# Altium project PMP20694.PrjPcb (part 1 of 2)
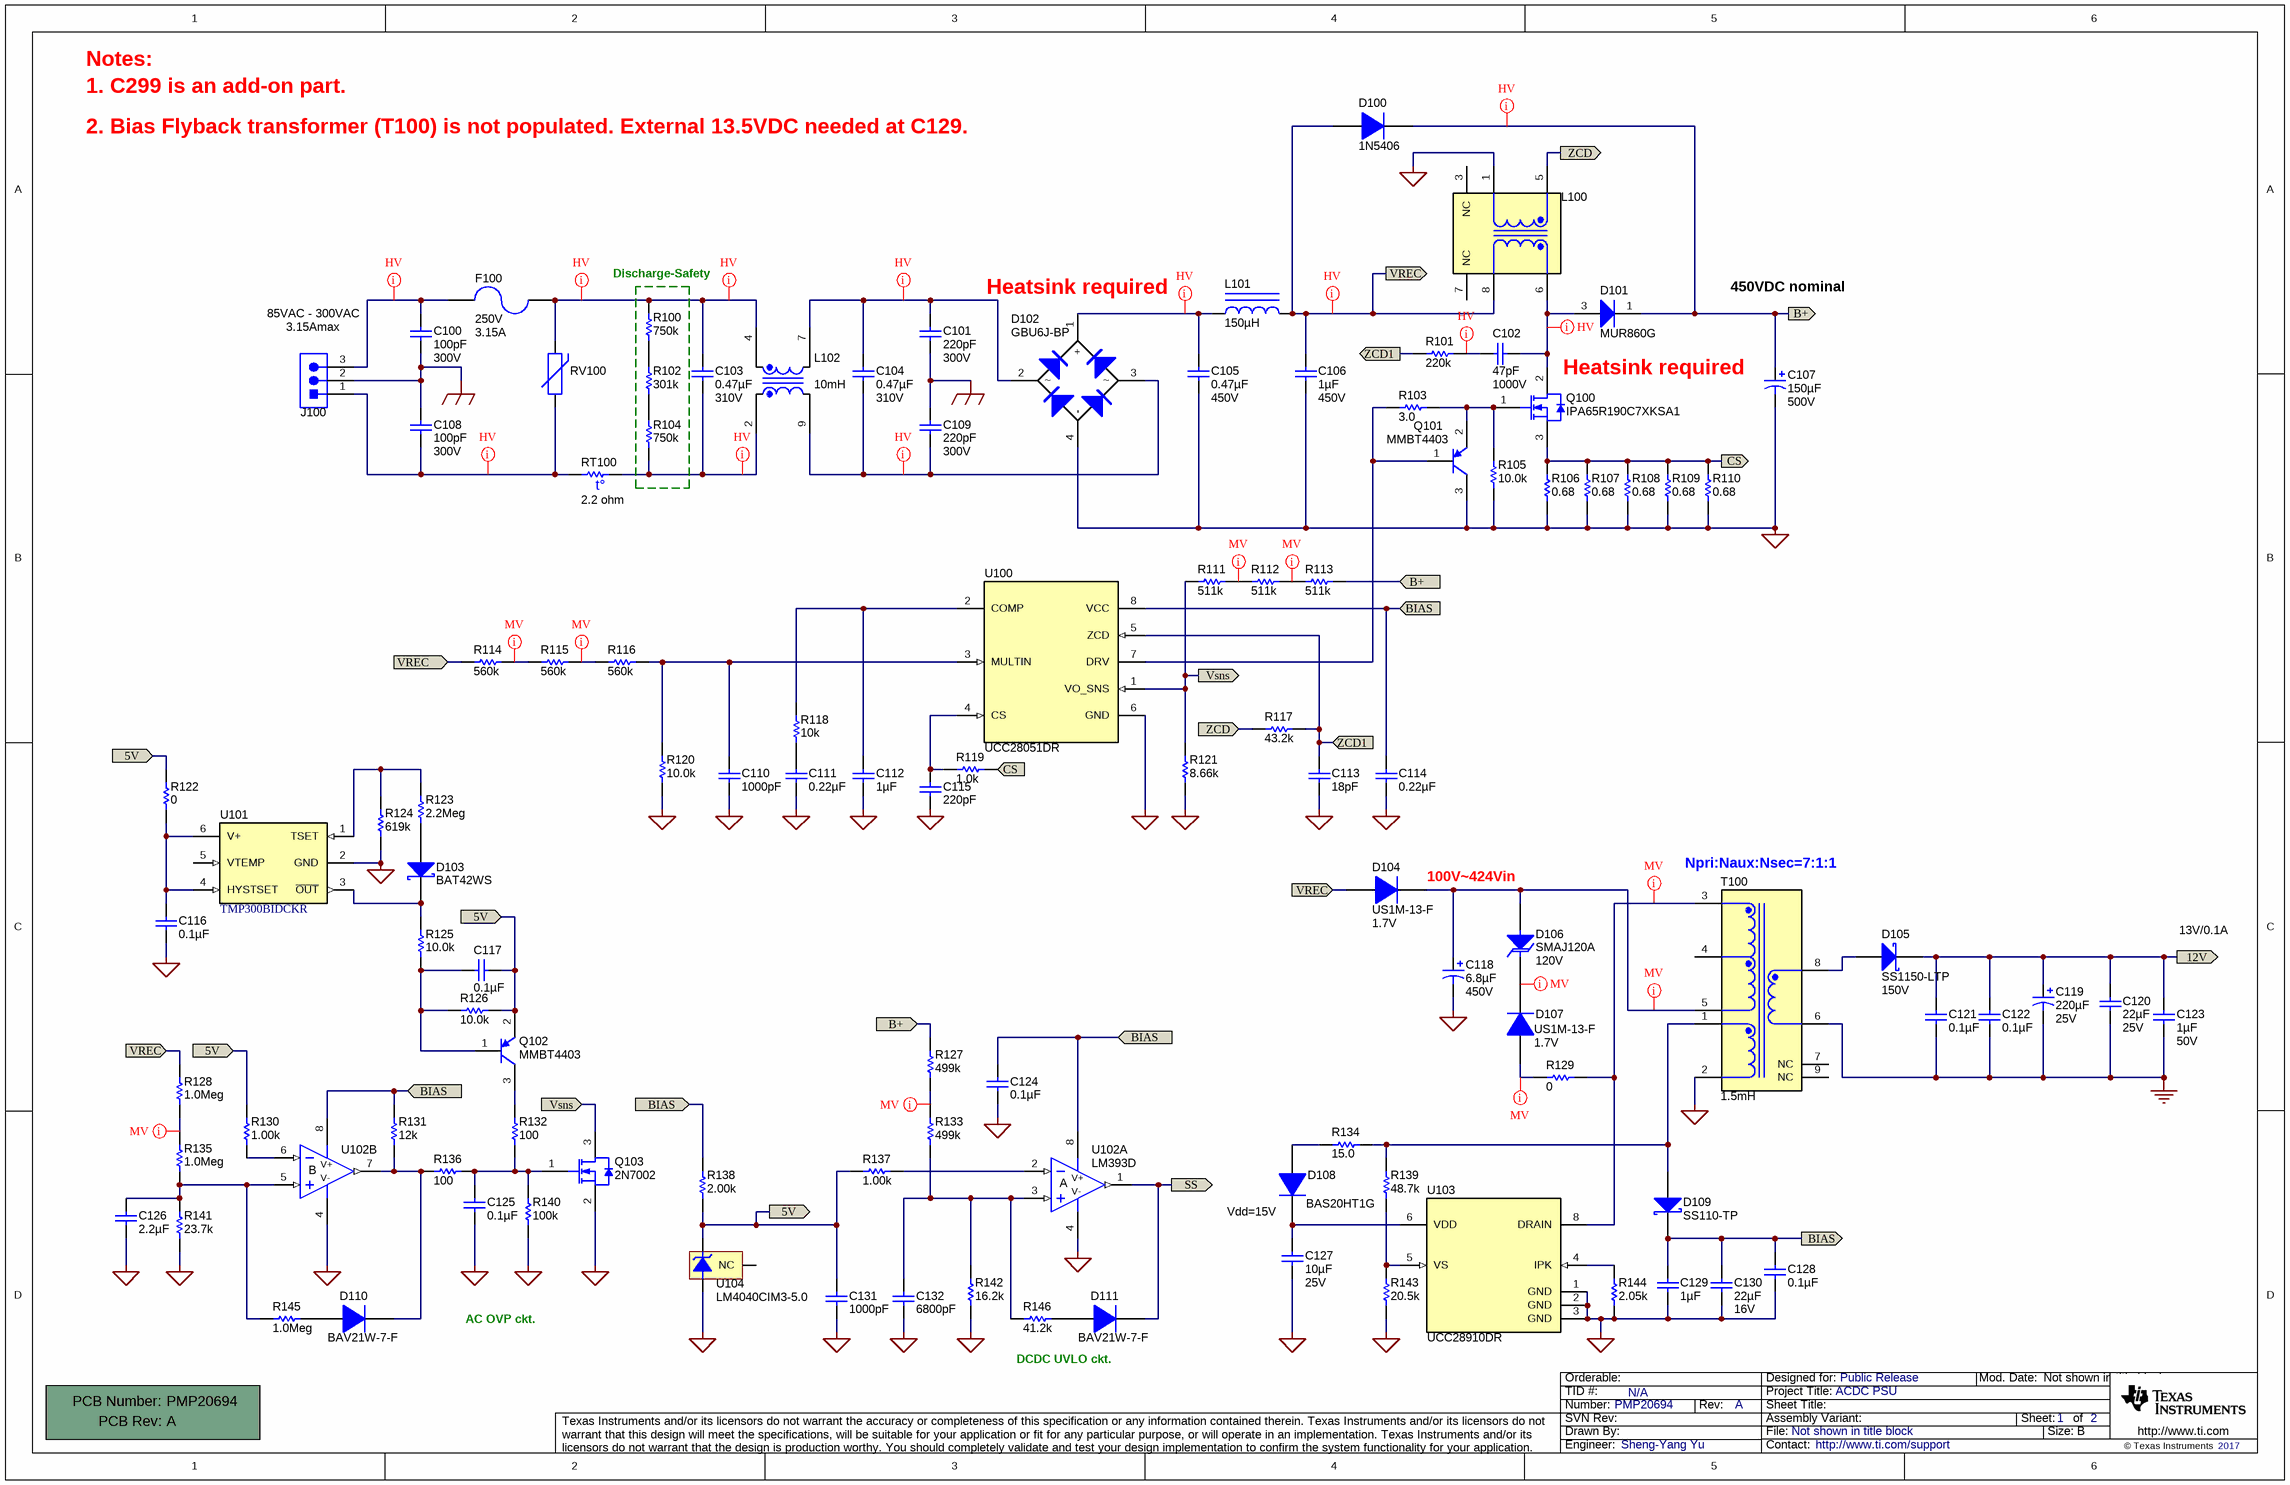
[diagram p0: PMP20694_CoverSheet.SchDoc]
CopyrightYear: 2017; PCB_Layout: Sheng-Yang Yu; PCB_Rev: A; PRJ_Customer: Public Release; PRJ_Engineer: Sheng-Yang Yu; PRJ_Number: PMP20694; PRJ_Title: ACDC PSU; SCH_Rev: A; TechSupport: http://www.ti.com/support; TID: N/A
2 sheets, 192 parts. Net scope: flat (ports and power ports of the same name join across sheets).
Board file: PMP20694_PCB.PcbDoc
Sheets:
  PMP20694_CoverSheet.SchDoc
  PMP20694_BlankSheet.SchDoc

## Sheet PMP20694_CoverSheet.SchDoc
size 431 x 279 mm; Date: Not shown in title block; ApprovedBy: Not shown in title block; CheckedBy: Not shown in title block; Author: Not shown in title block; CompanyName: Not shown in title block; Engineer: Not shown in title block; Organization: Not shown in title block; Address1: Not shown in title block; Address2: Not shown in title block; Address3: Not shown in title block; Address4: Not shown in title block; DocumentNumber: 1; Revision: Use project parameter SCH_Rev; SheetNumber: 1; SheetTotal: 2; PageSetup: Record=PageOptions¦CenterHorizontal=True¦CenterVertical=True¦PrintScale=1.00¦XCorrection=1.00¦YCorrection=1.00¦PrintKind=0¦BorderSize=5000000¦LeftOffset=0¦BottomOffset=0¦Orientation=2¦PaperLength=1000¦PaperWidth=1000¦Scale=100¦PaperSource=15¦PrintQuality=600¦MediaType=1¦DitherType=10¦PaperKind=Letter¦PrintScaleMode=1

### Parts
!PCB100  Printed Circuit Board  (value not drawn)  (mechanical)
C100  ValueDisplayed: 100pF  Value2: 300V  [CAPRD500W60D700H850]  (hidden comment: DE2B3KY101KN3AU02F)
C101  ValueDisplayed: 220pF  Value2: 300V  [CAPRD500W60D700H850]  (hidden comment: DE2B3KY221KN3AU02F)
C102  ValueDisplayed: 47pF  Value2: 1000V  [1206]  (hidden comment: GRM31A7U3A470JW31D)
C103  ValueDisplayed: 0.47µF  Value2: 310V  [WCAP-FTXX_P15xPL4]  (hidden comment: 890334025039CS)
C104  ValueDisplayed: 0.47µF  Value2: 310V  [WCAP-FTXX_P15xPL4]  (hidden comment: 890334025039CS)
C105  ValueDisplayed: 0.47µF  Value2: 450V  [MPK_1800x650]  (hidden comment: 450MPK474J)
C106  ValueDisplayed: 1µF  Value2: 450V  [MPK_1800x950]  (hidden comment: 450MPK105J)
C107  ValueDisplayed: 150µF  Value2: 500V  [SLPX_A5]  (hidden comment: 500MXG150MEFCSN22X55)
C108  ValueDisplayed: 100pF  Value2: 300V  [CAPRD500W60D700H850]  (hidden comment: DE2B3KY101KN3AU02F)
C109  ValueDisplayed: 220pF  Value2: 300V  [CAPRD500W60D700H850]  (hidden comment: DE2B3KY221KN3AU02F)
C110  ValueDisplayed: 1000pF  [0603]  (hidden comment: 06035A102KAT2A)
C111  ValueDisplayed: 0.22µF  [0603]  (hidden comment: 885012206048)
C112  ValueDisplayed: 1µF  [0603]  (hidden comment: C0603C105K8PACTU)
C113  ValueDisplayed: 18pF  [0603]  (hidden comment: 06035A180JAT2A)
C114  ValueDisplayed: 0.22µF  [1206]  (hidden comment: 12065C224KAT2A)
C115  ValueDisplayed: 220pF  [0603]  (hidden comment: 06035A221FAT2A)
C116  ValueDisplayed: 0.1µF  [0402]  (hidden comment: GRM155R61C104KA88D)
C117  ValueDisplayed: 0.1µF  [0402]  (hidden comment: GRM155R61C104KA88D)
C118  ValueDisplayed: 6.8µF  Value2: 450V  [B43888_1000x2000]  (hidden comment: UCA2W6R8MPD1TD)
C119  ValueDisplayed: 220µF  Value2: 25V  [CAPPRD350W60D800H1150]  (hidden comment: EEU-FM1E221)
C120  ValueDisplayed: 22µF  Value2: 25V  [1210_280]  (hidden comment: 12103D226MAT2A)
C121  ValueDisplayed: 0.1µF  [0603]  (hidden comment: 06033C104JAT2A)
C122  ValueDisplayed: 0.1µF  [0603]  (hidden comment: 06033C104JAT2A)
C123  ValueDisplayed: 1µF  Value2: 50V  [1206_180]  (hidden comment: CGA5L3X7R1H105K160AB)
C124  ValueDisplayed: 0.1µF  [0603]  (hidden comment: 06033D104KAT2A)
C125  ValueDisplayed: 0.1µF  [0603]  (hidden comment: 06033C104JAT2A)
C126  ValueDisplayed: 2.2µF  [0603]  (hidden comment: C0603C225K8PACTU)
C127  ValueDisplayed: 10µF  Value2: 25V  [1206_180]  (hidden comment: GRM31CR61E106KA12L)
C128  ValueDisplayed: 0.1µF  [0603]  (hidden comment: 06033C104JAT2A)
C129  ValueDisplayed: 1µF  [1206]  (hidden comment: GRM31MR71H105KA88L)
C130  ValueDisplayed: 22µF  Value2: 16V  [1206_190]  (hidden comment: 1206YD226MAT2A)
C131  ValueDisplayed: 1000pF  [0805_HV]  (hidden comment: 08051A102JAT2A)
C132  ValueDisplayed: 6800pF  [0603]  (hidden comment: C0603C682J5RACTU)
D100  1N5406  [DO-201AD]
D101  MUR860G  [TO-220AC]
D102  GBU6J-BP  [GBU]
D103  BAT42WS  [sod-323]
D104  US1M-13-F  value 1.7V  [SMA]
D105  SS1150-LTP  value 150V  [SMA]
D106  SMAJ120A  value 120V  [SMA]
D107  US1M-13-F  value 1.7V  [SMA]
D108  BAS20HT1G  [sod-323]
D109  SS110-TP  [SMA]
D110  BAV21W-7-F  [SOD-123]
D111  BAV21W-7-F  [SOD-123]
F100  VAC_V: 250V  Irating_A: 3.15A  [FUSE_372]  (hidden comment: 37213150001)
J100  1-1318301-3  [TE_1-1318301-3]  (value not drawn)
L100  PFC3125ER-231K06B-00  [TDK_PFC3125ER]  (value not drawn)
L101  ValueDisplayed: 150µH  [IND_7447020]  (hidden comment: 7447076)
L102  ValueDisplayed: 10mH  [IND_WE-CMB_L]  (hidden comment: 744824310)
Q100  IPA65R190C7XKSA1  [TO-220AB_100mil]
Q101  MMBT4403  [SOT-23]
Q102  MMBT4403  [SOT-23]
Q103  2N7002  [SOT-23]
R100  value 750k  [1206]  (hidden comment: CRCW1206750KFKEA)
R101  ValueDisplayed: 220k  [1206]  (hidden comment: CRCW1206220KJNEA)
R102  value 301k  [1206]  (hidden comment: CRCW1206301KFKEA)
R103  value 3.0  [0603]  (hidden comment: CRCW06033R00JNEA)
R104  value 750k  [1206]  (hidden comment: CRCW1206750KFKEA)
R105  value 10.0k  [1206]  (hidden comment: CRCW120610K0FKEA)
R106  ValueDisplayed: 0.68  [2512]  (hidden comment: ERJ-1TRQFR68U)
R107  ValueDisplayed: 0.68  [2512]  (hidden comment: ERJ-1TRQFR68U)
R108  ValueDisplayed: 0.68  [2512]  (hidden comment: ERJ-1TRQFR68U)
R109  ValueDisplayed: 0.68  [2512]  (hidden comment: ERJ-1TRQFR68U)
R110  ValueDisplayed: 0.68  [2512]  (hidden comment: ERJ-1TRQFR68U)
R111  value 511k  [1206]  (hidden comment: CRCW1206511KFKEA)
R112  value 511k  [1206]  (hidden comment: CRCW1206511KFKEA)
R113  value 511k  [1206]  (hidden comment: CRCW1206511KFKEA)
R114  value 560k  [0805_HV]  (hidden comment: CRCW0805560KJNEA)
R115  value 560k  [0805_HV]  (hidden comment: CRCW0805560KJNEA)
R116  value 560k  [0805_HV]  (hidden comment: CRCW0805560KJNEA)
R117  value 43.2k  [0603]  (hidden comment: CRCW060343K2FKEA)
R118  value 10k  [0603]  (hidden comment: CRCW060310K0JNEA)
R119  value 1.0k  [0603]  (hidden comment: CRCW06031K00JNEA)
R120  ValueDisplayed: 10.0k  [0603]  (hidden comment: CRCW060310K0FKEA)
R121  ValueDisplayed: 8.66k  [0603]  (hidden comment: CRCW06038K66FKEA)
R122  value 0  [0402]  (hidden comment: ERJ-2GE0R00X)
R123  value 2.2Meg  [0603]  (hidden comment: CRCW06032M20JNEA)
R124  value 619k  [0402]  (hidden comment: CRCW0402619KFKED)
R125  value 10.0k  [0402]  (hidden comment: CRCW040210K0FKED)
R126  value 10.0k  [0402]  (hidden comment: CRCW040210K0FKED)
R127  value 499k  [1206]  (hidden comment: CRCW1206499KFKEA)
R128  value 1.0Meg  [1206]  (hidden comment: CRCW12061M00JNEA)
R129  ValueDisplayed: 0  [1206]  (hidden comment: CRCW12060000Z0EA)
R130  ValueDisplayed: 1.00k  [0603]  (hidden comment: CRCW06031K00FKEA)
R131  ValueDisplayed: 12k  [0603]  (hidden comment: CRCW060312K0JNEA)
R132  value 100  [0402]  (hidden comment: CRCW0402100RFKED)
R133  value 499k  [1206]  (hidden comment: CRCW1206499KFKEA)
R134  value 15.0  [0603]  (hidden comment: CRCW060315R0FKEA)
R135  value 1.0Meg  [1206]  (hidden comment: CRCW12061M00JNEA)
R136  value 100  [0402]  (hidden comment: CRCW0402100RFKED)
R137  ValueDisplayed: 1.00k  [0603]  (hidden comment: CRCW06031K00FKEA)
R138  ValueDisplayed: 2.00k  [1206L]  (hidden comment: ERJ-8ENF2001V)
R139  ValueDisplayed: 48.7k  [0603]  (hidden comment: CRCW060348K7FKEA)
R140  value 100k  [0603]  (hidden comment: CRCW0603100KFKEA)
R141  ValueDisplayed: 23.7k  [0603]  (hidden comment: CRCW060323K7FKEA)
R142  ValueDisplayed: 16.2k  [0603]  (hidden comment: CRCW060316K2FKEA)
R143  ValueDisplayed: 20.5k  [0603]  (hidden comment: CRCW060320K5FKEA)
R144  ValueDisplayed: 2.05k  [0603]  (hidden comment: CRCW06032K05FKEA)
R145  value 1.0Meg  [1206]  (hidden comment: CRCW12061M00JNEA)
R146  ValueDisplayed: 41.2k  [0603]  (hidden comment: CRCW060341K2FKEA)
RT100  value 2.2 ohm  [S237]  (hidden comment: B57237S229M)
RV100  S10K275E2  [VAR_S10K275E2]  (value not drawn)
T100  ValueDisplayed: 1.5mH  [Wurth_EE13-7-4_5662]  (hidden comment: 750316711)
U100  UCC28051DR  [D0008A_N]
U101  TMP300BIDCKR  [DCK0006A_N]
U102  LM393D  [D0008A_N]  (parts A,B of 2)
U103  UCC28910DR  [D0007A_N]
U104  LM4040CIM3-5.0  [MF03A_N]

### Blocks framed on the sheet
Discharge-Safety: R100 R102 R104

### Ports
5V (in), 5V (out), 12V (out), B+ (in), B+ (out), BIAS (in), BIAS (out), CS (in), CS (out), SS (out), VREC (in), VREC (out), Vsns (in), Vsns (out), ZCD1 (in), ZCD1 (out), ZCD (in), ZCD (out)

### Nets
PE: C100.1 C101.1 C108.2 C109.2 J100.2
PGND: C105.2 C106.2 C107.2(-) C110.2 C111.2 C112.2 C113.2 C114.2 C115.2 C116.2 C118.2(-) C124.2 C125.2 C126.2 C127.1 C128.2 C129.2 C130.2 C131.2 C132.2 D102.4(-) L100.1 Q101.3(C) Q103.2(S) R105.1 R106.1 R107.1 R108.1 R109.1 R110.1 R120.1 R121.1 R124.1 R140.1 R141.1 R142.1 R143.1 R144.1 T100.2 U100.6(GND) U101.2(GND) U102.4(V-) U103.1(GND) U103.2(GND) U103.3(GND) U104.2(-V)
SGND: C119.2(-) C120.1 C121.2 C122.2 C123.2 T100.6
5V: C117.1 C131.1 Q102.2(E) R122.2 R126.2 R130.2 R137.2 R138.1 U104.1(+V) ; port 5V
12V: C119.1(+) C120.2 C121.1 C122.1 C123.1 D105.1(K) ; port 12V
B+: C107.1(+) D100.1(K) D101.1(K) R113.1 R127.2 ; port B+
BIAS: C114.1 C124.1 C128.1 C129.1 C130.1 D109.1(K) R131.2 R138.2 U100.8(VCC) U102.8(V+) ; port BIAS
CS: Q100.3(S) R106.2 R107.2 R108.2 R109.2 R110.2 R119.2 ; port CS
SS: D111.1(K) U102.1(OUT) ; port SS
VREC: C106.1 D100.2(A) D104.2(A) L100.8 L101.2 R114.2 R128.2 ; port VREC
Vsns: Q103.3(D) R111.2 R121.2 U100.1(VO_SNS) ; port Vsns
ZCD: L100.5 R117.1 ; port ZCD
ZCD1: C113.1 R101.1 R117.2 U100.5(ZCD) ; port ZCD1
NetC100_2: C100.2 F100.2 J100.3
NetC101_2: C101.2 C104.1 D102.2 L102.7
NetC102_1: C102.1 D101.3(A) L100.6 Q100.2(D)
NetC102_2: C102.2 R101.2
NetC103_1: C103.1 F100.1 L102.4 R100.2 RV100.2
NetC103_2: C103.2 L102.2 R104.1 RT100.2
NetC104_2: C104.2 C109.1 D102.3 L102.9
NetC105_1: C105.1 D102.1(+) L101.1
NetC108_1: C108.1 J100.1 RT100.1 RV100.1
NetC110_1: C110.1 R116.1 R120.2 U100.3(MULTIN)
NetC111_1: C111.1 R118.1
NetC112_1: C112.1 R118.2 U100.2(COMP)
NetC115_1: C115.1 R119.1 U100.4(CS)
NetC116_1: C116.1 R122.1 U101.4(HYSTSET) U101.6(V+)
NetC117_2: C117.2 Q102.1(B) R125.1 R126.1
NetC118_1: C118.1(+) D104.1(K) D106.2(A) T100.5
NetC125_1: C125.1 Q103.1(G) R132.1 R136.2 R140.2
NetC126_1: C126.1 R135.1 R141.2 R145.2 U102.5(IN+)
NetC127_2: C127.2 D108.1(K) U103.6(VDD)
NetC132_1: C132.1 R133.1 R142.2 R146.1 U102.3(IN+)
NetD103_1: D103.1(K) R125.2 U101.3(~{OUT})
NetD103_2: D103.2(A) R123.1
NetD105_2: D105.2(A) T100.8
NetD106_1: D106.1(K) D107.1(K)
NetD107_2: D107.2(A) R129.1
NetD108_2: D108.2(A) R134.2
NetD109_2: D109.2(A) R134.1 R139.2 T100.1
NetD110_1: D110.1(K) R131.1 R136.1 U102.7(OUT)
NetD110_2: D110.2(A) R145.1
NetD111_2: D111.2(A) R146.2
NetQ100_1: Q100.1(G) Q101.2(E) R103.2 R105.2
NetQ101_1: Q101.1(B) R103.1 U100.7(DRV)
NetQ102_3: Q102.3(C) R132.2
NetR100_1: R100.1 R102.2
NetR102_1: R102.1 R104.2
NetR111_1: R111.1 R112.2
NetR112_1: R112.1 R113.2
NetR114_1: R114.1 R115.2
NetR115_1: R115.1 R116.2
NetR123_2: R123.2 R124.2 U101.1(TSET)
NetR127_1: R127.1 R133.2
NetR128_1: R128.1 R135.2
NetR129_2: R129.2 T100.3 U103.8(DRAIN)
NetR130_1: R130.1 U102.6(IN-)
NetR137_1: R137.1 U102.2(IN-)
NetR139_1: R139.1 R143.2 U103.5(VS)
NetR144_2: R144.2 U103.4(IPK)

Not connected (* = marked no-connect by the designer): L100 3(NC) 7(NC); T100 4 7(NC) 9(NC); U101 5(VTEMP); U104 3(NC)

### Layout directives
net class HV: B+, NetC100_2, NetC101_2, NetC102_1, NetC102_2, NetC103_1, NetC103_2, NetC104_2, NetC105_1, NetC108_1, VREC
net class MV: NetC118_1, NetD106_1, NetD107_2, NetR111_1, NetR112_1, NetR114_1, NetR115_1, NetR127_1, NetR128_1, NetR129_2

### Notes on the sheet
- Notes:
- 1. C299 is an add-on part.
- 2. Bias Flyback transformer (T100) is not populated. External 13.5VDC needed at C129.
- Heatsink required
- 450VDC nominal
- 85VAC - 300VAC
- (near J100) 3.15Amax
- (near D104) 100V~424Vin
- (near T100) Npri:Naux:Nsec=7:1:1
- 13V/0.1A
- (near D108) Vdd=15V
- AC OVP ckt.
- DCDC UVLO ckt.

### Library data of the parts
!PCB100 = PCB: Manufacturer: Any; PartNumber: PMP20694; SymbolCreator: a0412235
C100 C108 = DE2B3KY101KA2BM01: CAP CER 100PF 300VAC RADIAL; Manufacturer: MuRata; Polarized: N; CompType: Capacitor; U/M: EA; Cap_F: 0.0000000001; Tolerance_%: 10; Value1: Unknown; TempCo: B; TaMin_C: -25; TaMax_C: 85; SizeArea_mm2: 35; SizeAreaWB_mm2: 63; SizeX_mm: 7; SizeY_mm: 5; AEC Category: Q200
C101 C109 = DE2B3KY101KA2BM01: CAP CER 220PF 300VAC RADIAL; Manufacturer: MuRata; Polarized: N; CompType: Capacitor; U/M: EA; Cap_F: 0.0000000001; Tolerance_%: 10; Value1: Unknown; TempCo: B; TaMin_C: -25; TaMax_C: 85; SizeArea_mm2: 35; SizeAreaWB_mm2: 63; SizeX_mm: 7; SizeY_mm: 5; AEC Category: Q200
C102 = GRM31A7U3A470JW31D: CAP, CERM, 47 pF, 1000 V, +/- 5%, U2J, 1206; Manufacturer: MuRata; Polarized: N; CompType: Capacitor; Value: 47pF; U/M: EA; Cap_F: 0.000000000047; Tolerance_%: 5; Value1: Unknown; VDC_V: 1000; TaMin_C: -55; TaMax_C: 125; SizeArea_mm2: 5.12; SizeAreaWB_mm2: 10.92; SizeX_mm: 3.2; SizeY_mm: 1.6; SizeZ_mm: 1.35; AEC Category: Q200
C103 C104 = 890334025039CS: CAP, Film, 0.47 µF, 310 V, +/- 10%, TH; Manufacturer: Wurth Elektronik; Polarized: N; CompType: Capacitor; Value: 0.47uF; U/M: EA; Cap_F: 0.00000047; Tolerance_%: 10; Value1: Unknown; VDC_V: 310; TaMin_C: -40; TaMax_C: 105; Cap_Case: 18x8mm; AEC Category: Q200
C105 = 450MPK474J: CAP, Film, 0.47 µF, 450 V, +/- 5%, TH; Manufacturer: Rubycon; Polarized: N; CompType: Capacitor; Value: 0.47uF; U/M: EA; Cap_F: 0.00000047; Tolerance_%: 5; Value1: Unknown; VDC_V: 450; TaMin_C: -40; TaMax_C: 105; Cap_Case: 18x6.5mm; AEC Category: Q200
C106 = 450MPK105J: CAP, Film, 1 µF, 450 V, +/- 5%, TH; Manufacturer: Rubycon; Polarized: N; CompType: Capacitor; Value: 1uF; U/M: EA; Cap_F: 0.000001; Tolerance_%: 5; Value1: Unknown; VDC_V: 450; TaMin_C: -40; TaMax_C: 105; Cap_Case: 18x9.5mm; AEC Category: Q200
C107 = SLPX151M400A5P3: CAP ALUM 150UF 20% 500V SNAP; Manufacturer: Rubycon; Polarized: Y; CompType: Capacitor; U/M: EA; Cap_F: 0.00015; Tolerance_%: 20; Value1: 1.327 ohm; VDC_V: 500; ESR_ohm: 1.327; IRMS_A: 1.24; TaMin_C: -25; TaMax_C: 105; Cap_Case: 22x35mm; SizeAreaWB_mm2: 576; SizeArea_mm2: 484; SizeX_mm: 22; SizeZ_mm: 37; AEC Category: Q200; AEC Qualified: N
C110 = 06035A102KAT2A: CAP, CERM, 1000pF, 50V, +/-10%, C0G/NP0, 0603; Manufacturer: AVX; Polarized: N; CompType: Capacitor; U/M: EA; Cap_F: 0.000000001; Tolerance_%: 10; ESR_Ohm: 0.048; Value1: 0.048 ohm; VDC_V: 50; TaMin_C: -55; TaMax_C: 125
C111 = 885012206048: CAP, CERM, 0.22 µF, 16 V, +/- 10%, X7R, 0603; Manufacturer: Wurth Elektronik; Polarized: N; CompType: Capacitor; Value: 0.22uF; U/M: EA; Cap_F: 0.00000022; Tolerance_%: 10; Value1: Unknown; VDC_V: 16; Value2: 16V; TaMin_C: -55; TaMax_C: 125; SizeArea_mm2: 1.28; SizeAreaWB_mm2: 4.68; SizeX_mm: 1.6; SizeY_mm: 0.8; SizeZ_mm: 1; AEC Category: Q200
C112 = C0603C105K8PACTU: CAP, CERM, 1uF, 10V, +/-10%, X5R, 0603; Manufacturer: Kemet; Polarized: N; CompType: Capacitor; U/M: EA; Cap_F: 0.000001; Tolerance_%: 10; Value1: Unknown; TaMin_C: -55; TaMax_C: 85
C113 = 06035A180JAT2A: CAP, CERM, 18pF, 50V, +/-5%, C0G/NP0, 0603; Manufacturer: AVX; Polarized: N; CompType: Capacitor; U/M: EA; Cap_F: 0.000000000018; Tolerance_%: 5; ESR_Ohm: 0.289; Value1: 0.289 ohm; VDC_V: 50; TaMin_C: -55; TaMax_C: 125
C114 = 12065C224KAT2A: CAP, CERM, 0.22uF, 50V, +/-10%, X7R, 1206; Manufacturer: AVX; Polarized: N; CompType: Capacitor; U/M: EA; Cap_F: 0.00000022; Tolerance_%: 10; ESR_Ohm: 0.026; Value1: 0.026 ohm; VDC_V: 50; TaMin_C: -55; TaMax_C: 125
C115 = 06035A221FAT2A: CAP, CERM, 220pF, 50V, +/-1%, C0G/NP0, 0603; Manufacturer: AVX; Polarized: N; CompType: Capacitor; U/M: EA; Cap_F: 0.00000000022; Tolerance_%: 1; ESR_Ohm: 0.083; Value1: 0.083 ohm; VDC_V: 50; TaMin_C: -55; TaMax_C: 125
C116 C117 = GRM155R61C104KA88D: CAP, CERM, 0.1uF, 16V, +/-10%, X5R, 0402; Manufacturer: MuRata; Polarized: N; CompType: Capacitor; U/M: EA; Cap_F: 0.0000001; Tolerance_%: 10; Value1: Unknown; VDC_V: 16; TaMin_C: -55; TaMax_C: 85
C118 = B43888G5685M000: CAP ALUM 6.8UF 20% 450V RADIAL; Manufacturer: Nichicon; Polarized: Y; CompType: Capacitor; U/M: EA; Cap_F: 0.0000068; Tolerance_%: 20; Value1: 58.5 ohm; VDC_V: 450; ESR_ohm: 58.5; IRMS_A: 0.2; TaMax_C: 105; Cap_Case: 10x20mm; SizeAreaWB_mm2: 144; SizeArea_mm2: 100; SizeX_mm: 10; SizeZ_mm: 22; AEC Category: Q200; AEC Qualified: N
C119 = 200LLE10MEFC8X11.5: CAP ALUM 220UF 25V 20% RADIAL; Manufacturer: Panasonic; Polarized: Y; CompType: Capacitor; U/M: EA; Cap_F: 0.00001; Tolerance_%: 20; Value1: Unknown; VDC_V: 25; IRMS_A: 0.08; TaMin_C: -40; TaMax_C: 105; Cap_Case: Radial 8x11.5mm
C120 = 12103D226MAT2A: CAP, CERM, 22 µF, 25 V, +/- 20%, X5R, 1210; Manufacturer: AVX; Polarized: N; CompType: Capacitor; Value: 22uF; U/M: EA; Cap_F: 0.000022; Tolerance_%: 20; Value1: Unknown; VDC_V: 25; TaMin_C: -55; TaMax_C: 85; Cap_Case: 1210; SizeArea_mm2: 8; SizeAreaWB_mm2: 14.7; SizeX_mm: 3.2; SizeY_mm: 2.5; SizeZ_mm: 2.8; AEC Category: Q200
C121 C122 C125 = 06033C104JAT2A: CAP, CERM, 0.1uF, 25V, +/-5%, X7R, 0603; Manufacturer: AVX; Polarized: N; CompType: Capacitor; U/M: EA; Cap_F: 0.0000001; Tolerance_%: 5; ESR_Ohm: 0.05; Value1: 0.05 ohm; VDC_V: 25; TaMin_C: -55; TaMax_C: 125
C123 = CGA5L3X7R1H105K160AB: CAP, CERM, 1 µF, 50 V, +/- 10%, X7R, AEC-Q200 Grade 1, 1206; Manufacturer: TDK; Polarized: N; CompType: Capacitor; Value: 1uF; U/M: EA; Cap_F: 0.000001; Tolerance_%: 10; ESR_ohm: 0.009289; Value1: 0.009289 ohm; VDC_V: 50; IRMS_A: 2.38446; TaMin_C: -55; TaMax_C: 125; SizeArea_mm2: 5.12; SizeAreaWB_mm2: 10.92; SizeX_mm: 3.2; SizeY_mm: 1.6; SizeZ_mm: 1.8; AEC Category: Q200; AEC Qualified: Y; AEC Grade: 1
C124 = 06033D104KAT2A: CAP, CERM, 0.1uF, 25V, +/-10%, X5R, 0603; Manufacturer: AVX; Polarized: N; CompType: Capacitor; U/M: EA; Cap_F: 0.0000001; Tolerance_%: 10; ESR_Ohm: 0.048; Value1: 0.048 ohm; VDC_V: 25; IRMS_A: 0.53; TaMin_C: -55; TaMax_C: 85
C126 = C0603C225K8PACTU: CAP, CERM, 2.2uF, 10V, +/-10%, X5R, 0603; Manufacturer: Kemet; Polarized: N; CompType: Capacitor; U/M: EA; Cap_F: 0.0000022; Tolerance_%: 10; Value1: Unknown; TaMin_C: -55; TaMax_C: 85
C127 = GRM31CR61E106KA12L: CAP, CERM, 10 µF, 25 V, +/- 10%, X5R, 1206; Manufacturer: MuRata; Polarized: N; CompType: Capacitor; Value: 10uF; U/M: EA; Cap_F: 0.00001; Tolerance_%: 10; ESR_ohm: 0.004; Value1: 0.004 ohm; VDC_V: 25; TaMin_C: -55; TaMax_C: 85; Cap_Case: 1206; SizeArea_mm2: 5.12; SizeAreaWB_mm2: 10.92; SizeX_mm: 3.2; SizeY_mm: 1.6; SizeZ_mm: 1.8; AEC Category: Q200
C128 = 06033C104JAT2A: CAP, CERM, 0.1 µF, 25 V, +/- 5%, X7R, 0603; Manufacturer: AVX; Polarized: N; CompType: Capacitor; Value: 0.1uF; U/M: EA; Cap_F: 0.0000001; Tolerance_%: 5; ESR_ohm: 0.05; Value1: 0.05 ohm; VDC_V: 25; Value2: 25V; TaMin_C: -55; TaMax_C: 125
C129 = GRM31MR71H105KA88L: CAP, CERM, 1 µF, 50 V, +/- 10%, X7R, 1206; Manufacturer: MuRata; Polarized: N; CompType: Capacitor; Value: 1uF; U/M: EA; Cap_F: 0.000001; Tolerance_%: 10; Value1: Unknown; VDC_V: 50; Value2: 50V; TaMin_C: -55; TaMax_C: 125
C130 = 1206YD226MAT2A: CAP, CERM, 22 µF, 16 V, +/- 20%, X5R, 1206_190; Manufacturer: AVX; Polarized: N; CompType: Capacitor; Value: 22uF; U/M: EA; Cap_F: 0.000022; Tolerance_%: 20; Value1: Unknown; VDC_V: 16; TaMin_C: -55; TaMax_C: 85; Cap_Case: 1206; SizeArea_mm2: 5.12; SizeAreaWB_mm2: 10.92; SizeX_mm: 3.2; SizeY_mm: 1.6; SizeZ_mm: 1.9; AEC Category: Q200
C131 = 08051A102JAT2A: CAP, CERM, 1000 pF, 100 V, +/- 5%, C0G/NP0, 0805; Manufacturer: AVX; Polarized: N; CompType: Capacitor; Value: 1000pF; U/M: EA; Cap_F: 0.000000001; Tolerance_%: 5; ESR_ohm: 0.112; Value1: 0.112 ohm; VDC_V: 100; Value2: 100V; TaMin_C: -55; TaMax_C: 125; Cap_Case: 0805; SizeArea_mm2: 2.5; SizeAreaWB_mm2: 6.75; SizeX_mm: 2; SizeY_mm: 1.25; SizeZ_mm: 1.45; AEC Category: Q200
C132 = C0603C682J5RACTU: CAP, CERM, 6800pF, 50V, +/-5%, X7R, 0603; Manufacturer: Kemet; Polarized: N; CompType: Capacitor; U/M: EA; Cap_F: 0.0000000068; Tolerance_%: 5; Value1: Unknown; VDC_V: 50; TaMin_C: -55; TaMax_C: 125
D100 = 1N5406: Diode, Switching-Bridge, 600V, 3A, TH; Manufacturer: Vishay-Semiconductor; Value: 1.2V; U/M: EA; Vf_V: 1.2; Io_A: 3; Vr_V: 600; TJmax_C: 150
D101 = MUR860G: Diode, Ultrafast, 600V, 8A, TH; Manufacturer: ON Semiconductor; SymbolCreator: a0412235; Value: 0.98V; U/M: EA; Vf_V: 0.98; Io_A: 8; Vr_V: 600; TJmax_C: 175; RJC_CperW: 4.75
D102 = GBU8J-BP: Diode, Switching-Bridge, 420 V, 6 A, TH; Manufacturer: Micro Commercial Components; U/M: EA; Vf_V: 1; Value: 420V; Value1: 6A; Value2: 1V; Io_A: 8; Vr_V: 420; TJmax_C: 175; SizeAreaWB_mm2: 130.5915; SizeArea_mm2: 75.6315; SizeX_mm: 22.05; SizeY_mm: 3.43; SizeZ_mm: 21.55; AEC Category: Q101
D103 = BAT42WS-7-F: Diode, Schottky, 30V, 0.2A, SOD-323; Manufacturer: Diodes Inc.; Value: 1V; U/M: EA; Vf_V: 1; Io_A: 0.2; Vr_V: 30
D104 D107 = US1M-13-F: Diode, Ultrafast, 1000V, 1A, SMA; Manufacturer: Diodes Inc.; U/M: EA; Vf_V: 1.7; Io_A: 1; Vr_V: 1000; TJmax_C: 150; RJC_CperW: 30
D105 = SS110-TP: DIODE SCHOTTKY 150V 1A DO214AC; Manufacturer: Micro Commercial Components; U/M: EA; Vf_V: 0.85; Value2: 0.85V; Io_A: 1; Vr_V: 150; TJmax_C: 125
D106 = SMAJ120A: Diode, TVS, Uni, 120 V, SMA; Manufacturer: Littelfuse; U/M: EA; Power_W: 3.3; Vr_V: 120; Value1: 3.3W; SizeAreaWB_mm2: 37.3428; SizeArea_mm2: 16.3228; SizeX_mm: 5.59; SizeY_mm: 2.92; SizeZ_mm: 2.87; AEC Category: Q101
D108 = BAS316,115: DIODE SWITCH 200V 200MA SOD323; U/M: EA; Vf_V: 1.4; Value1: 0.25A; Vr_V: 100; Value2: 100V; TJmax_C: 150; Type: Ultrafast
D109 = SS110-TP: Diode, Schottky, 100 V, 1 A, SMA; Manufacturer: Micro Commercial Components; U/M: EA; Vf_V: 0.85; Value: 100V; Value1: 1A; Value2: 0.85V; Io_A: 1; Vr_V: 100; TJmax_C: 125
D110 D111 = BAV21W-7-F: Diode, Switching, 200V, 0.2A, SOD-123; Manufacturer: Diodes Inc.; U/M: EA; Vf_V: 1.25; Value2: 1.25V; Io_A: 0.2; Vr_V: 200; TJmax_C: 150
F100 = 37213150001: Fuse, 3.15 A, 250VAC/VDC, TH; Manufacturer: Littelfuse; VDC_V: 250
J100 = 1-1318301-3: Header, 312mil, 3x1, Tin, TH; Manufacturer: TE Connectivity; SymbolCreator: a0799628
L100 = PFC3125ER-231K06B-00: Transformer, 230 uH, TH; Manufacturer: TDK; SymbolCreator: Altium; Lp: 230; Ns1toNp: 9; SizeAreaWB_mm2: 980; SizeArea_mm2: 858; SizeX_mm: 26; SizeY_mm: 33; SizeZ_mm: 27
L101 = 7447020: Inductor, Toroid, Powdered Iron, 150 µH, 5A, TH; Manufacturer: Wurth Elektronik; Value: 150uH; Value1: 0.16 ohm
L102 = 744824310: Coupled inductor, 10 mH, 3 A, 0.105 ohm, TH; Manufacturer: Wurth Elektronik; SymbolCreator: a0799628; Value: 10mH; Ind_H: 10.0E-3; DCR_ohm: 0.105
Q100 = IPP50R199CP: MOSFET N-CH 650V 8A TO220; Manufacturer: Infineon Technologies; Alternate Manufacturer: None; U/M: EA; ChType: N; Value1: ? ohm; Rdson45_Ohm: 0; QgTyp_nC: 34; IdsMax_A: 17
Q101 = MMBT4403, Fairchild Semiconductor: Transistor, PNP, 40 V, 0.6 A, SOT-23; CompType: BJT; PNP: 1; NPN: 0; Vceo_V: 40; Vcesat1_V: 0.75; Value: 40 V; IcRated_A: 0.6; Value1: 0.6 A; HfeMax: 500; TaMin_C: -55; TaMax_C: 150; SizeAreaWB_mm2: 14; SizeArea_mm2: 7.5; SizeX_mm: 2.5; SizeY_mm: 3; SizeZ_mm: 1.1; U/M: EA; AEC Category: Q101
Q102 = MMBT4403, Fairchild Semiconductor: Transistor, PNP, 40V, 0.6A, SOT-23; Alternate Manufacturer: None; CompType: BJT; U/M: EA; PNP: 1; NPN: 0; Vceo_V: 40; Vcesat1_V: 0.75; Value: 0.75V; IcRated_A: 0.6; HfeMax: 500
Q103 = 2N7002: MOSFET, N-CH, 60 V, 115 A, SOT-23; Manufacturer: Fairchild Semiconductor; Alternate Manufacturer: None; U/M: EA; ChType: N; Value: 60V; VdsMax_V: 60; Value1: ? ohm; Value2: ? nC; Vgs_V: 20; IdsMax_A: 115; SizeAreaWB_mm2: 14; SizeArea_mm2: 7.5; SizeX_mm: 2.5; SizeY_mm: 3; SizeZ_mm: 1.1; AEC Category: Q101
R100 R104 = CRCW1206750KFKEA: RES, 750k ohm, 1%, 0.25W, 1206; Manufacturer: Vishay-Dale; CompType: Resistor; Res_ohm: 750000; Tolerance_%: 1; Power_W: 0.25; VDC_V: 200; TempCo: 100 ppm/C; EIA_Code: E96; U/M: EA
R101 = CRCW1206220KJNEA: RES, 220 k, 5%, 0.25 W, 1206; Manufacturer: Vishay-Dale; CompType: Resistor; Value: 220k; Res_ohm: 220000; Tolerance_%: 5; Power_W: 0.25; Value2: 0.25W; VDC_V: 200; TempCo: 200 ppm/C; SizeArea_mm2: 5.12; SizeX_mm: 3.2; SizeY_mm: 1.6; SizeZ_mm: 1.35; EIA_Code: E24; U/M: EA; AEC Category: Q200
R102 = CRCW1206301KFKEA: RES, 301k ohm, 1%, 0.25W, 1206; Manufacturer: Vishay-Dale; CompType: Resistor; Res_ohm: 301000; Tolerance_%: 1; Power_W: 0.25; VDC_V: 200; TempCo: 100 ppm/C; EIA_Code: E96; U/M: EA
R103 = CRCW06033R00JNEA: RES, 3.0 ohm, 5%, 0.1W, 0603; Manufacturer: Vishay-Dale; CompType: Resistor; Res_ohm: 3; Value_Code: 3R00; Tolerance_%: 5; Power_W: 0.1; VDC_V: 75; TempCo: 200 ppm/C; EIA_Code: E24; U/M: EA
R105 = CRCW120610K0FKEA: RES, 10.0k ohm, 1%, 0.25W, 1206; Manufacturer: Vishay-Dale; CompType: Resistor; Res_ohm: 10000; Value_Code: 10k0; Tolerance_%: 1; Power_W: 0.25; VDC_V: 200; TempCo: 100 ppm/C; EIA_Code: E96; U/M: EA
R106-R110 = ERJ-1TRQFR68U: RES, 0.68, 1%, 1 W, 2512; Manufacturer: Panasonic; CompType: Resistor; Value: 0.68; Value_Code: R680; Tolerance_%: 1; Value2: 1W; TempCo: 200 ppm/C; SizeArea_mm2: 20.16; SizeX_mm: 6.3; SizeY_mm: 3.2; SizeZ_mm: 0.71; EIA_Code: E96; U/M: EA; AEC Category: Q200
R111-R113 = CRCW1206511KFKEA: RES, 511k ohm, 1%, 0.25W, 1206; Manufacturer: Vishay-Dale; CompType: Resistor; Res_ohm: 511000; Tolerance_%: 1; Power_W: 0.25; VDC_V: 200; TempCo: 100 ppm/C; EIA_Code: E96; U/M: EA
R114-R116 = CRCW0805560KJNEA: RES, 560k ohm, 5%, 0.125W, 0805; Manufacturer: Vishay-Dale; CompType: Resistor; Res_ohm: 560000; Tolerance_%: 5; Power_W: 0.125; VDC_V: 150; TempCo: 200 ppm/C; EIA_Code: E24; U/M: EA
R117 = CRCW060343K2FKEA: RES, 43.2k ohm, 1%, 0.1W, 0603; Manufacturer: Vishay-Dale; CompType: Resistor; Res_ohm: 43200; Value_Code: 43k2; Tolerance_%: 1; Power_W: 0.1; VDC_V: 75; TempCo: 100 ppm/C; EIA_Code: E96; U/M: EA
R118 = CRCW060310K0JNEA: RES, 10k ohm, 5%, 0.1W, 0603; Manufacturer: Vishay-Dale; CompType: Resistor; Res_ohm: 10000; Value_Code: 10k0; Tolerance_%: 5; Power_W: 0.1; VDC_V: 75; TempCo: 200 ppm/C; EIA_Code: E24; U/M: EA
R119 = CRCW06031K00JNEA: RES, 1.0k ohm, 5%, 0.1W, 0603; Manufacturer: Vishay-Dale; CompType: Resistor; Res_ohm: 1000; Value_Code: 1k00; Tolerance_%: 5; Power_W: 0.1; VDC_V: 75; TempCo: 200 ppm/C; EIA_Code: E24; U/M: EA
R120 = CRCW060310K0FKEA: RES, 10.0 k, 1%, 0.1 W, 0603; Manufacturer: Vishay-Dale; CompType: Resistor; Value: 10.0k; Res_ohm: 10000; Value_Code: 10k0; Tolerance_%: 1; Power_W: 0.1; Value2: 0.1W; VDC_V: 75; TempCo: 100 ppm/C; SizeArea_mm2: 1.28; SizeX_mm: 1.6; SizeY_mm: 0.8; EIA_Code: E96; U/M: EA; AEC Category: Q200
R121 = CRCW06038K66FKEA: RES, 8.66 k, 1%, 0.1 W, 0603; Manufacturer: Vishay-Dale; CompType: Resistor; Value: 8.66k; Res_ohm: 8660; Value_Code: 8k66; Tolerance_%: 1; Power_W: 0.1; Value2: 0.1W; VDC_V: 75; TempCo: 100 ppm/C; SizeArea_mm2: 1.28; SizeX_mm: 1.6; SizeY_mm: 0.8; EIA_Code: E96; U/M: EA; AEC Category: Q200
R122 = ERJ-2GE0R00X: RES, 0 ohm, 5%, 0.063W, 0402; Manufacturer: Panasonic; CompType: Resistor; Value_Code: 0000; Tolerance_%: 5; Power_W: 0.063; VDC_V: 50; TempCo: 600 ppm/C; EIA_Code: E24; U/M: EA
R123 = CRCW06032M20JNEA: RES, 2.2Meg ohm, 5%, 0.1W, 0603; Manufacturer: Vishay-Dale; CompType: Resistor; Res_ohm: 2200000; Value_Code: 2M20; Tolerance_%: 5; Power_W: 0.1; VDC_V: 75; TempCo: 200 ppm/C; EIA_Code: E24; U/M: EA
R124 = CRCW0402619KFKED: RES, 619k ohm, 1%, 0.063W, 0402; Manufacturer: Vishay-Dale; CompType: Resistor; Res_ohm: 619000; Tolerance_%: 1; Power_W: 0.063; VDC_V: 50; TempCo: 100 ppm/C; EIA_Code: E96; U/M: EA
R125 R126 = CRCW040210K0FKED: RES, 10.0k ohm, 1%, 0.063W, 0402; Manufacturer: Vishay-Dale; CompType: Resistor; Res_ohm: 10000; Value_Code: 10k0; Tolerance_%: 1; Power_W: 0.063; VDC_V: 50; TempCo: 100 ppm/C; EIA_Code: E96; U/M: EA
R127 R133 = CRCW1206499KFKEA: RES, 499k ohm, 1%, 0.25W, 1206; Manufacturer: Vishay-Dale; CompType: Resistor; Res_ohm: 499000; Tolerance_%: 1; Power_W: 0.25; VDC_V: 200; TempCo: 100 ppm/C; EIA_Code: E96; U/M: EA
R128 R135 R145 = CRCW12061M00JNEA: RES, 1.0Meg ohm, 5%, 0.25W, 1206; Manufacturer: Vishay-Dale; CompType: Resistor; Res_ohm: 1000000; Value_Code: 1M00; Tolerance_%: 5; Power_W: 0.25; VDC_V: 200; TempCo: 200 ppm/C; EIA_Code: E24; U/M: EA
R129 = CRCW12060000Z0EA: RES, 0, 5%, 0.25 W, 1206; Manufacturer: Vishay-Dale; CompType: Resistor; Value: 0; Value_Code: 0000; Tolerance_%: 5; Power_W: 0.25; Value2: 0.25W; VDC_V: 200; TempCo: 200 ppm/C; SizeArea_mm2: 5.12; SizeX_mm: 3.2; SizeY_mm: 1.6; SizeZ_mm: 1.35; EIA_Code: E24; U/M: EA; AEC Category: Q200
R130 R137 = CRCW06031K00FKEA: RES, 1.00 k, 1%, 0.1 W, 0603; Manufacturer: Vishay-Dale; CompType: Resistor; Value: 1.00k; Res_ohm: 1000; Value_Code: 1k00; Tolerance_%: 1; Power_W: 0.1; Value2: 0.1W; VDC_V: 75; TempCo: 100 ppm/C; SizeArea_mm2: 1.28; SizeX_mm: 1.6; SizeY_mm: 0.8; EIA_Code: E96; U/M: EA; AEC Category: Q200
R131 = CRCW060312K0JNEA: RES, 12 k, 5%, 0.1 W, 0603; Manufacturer: Vishay-Dale; CompType: Resistor; Value: 12k; Res_ohm: 12000; Value_Code: 12k0; Tolerance_%: 5; Power_W: 0.1; Value2: 0.1W; VDC_V: 75; TempCo: 200 ppm/C; SizeArea_mm2: 1.28; SizeX_mm: 1.6; SizeY_mm: 0.8; SizeZ_mm: 1; EIA_Code: E24; U/M: EA; AEC Category: Q200
R132 R136 = CRCW0402100RFKED: RES, 100 ohm, 1%, 0.063W, 0402; Manufacturer: Vishay-Dale; CompType: Resistor; Value_Code: 100R; Tolerance_%: 1; Power_W: 0.063; VDC_V: 50; TempCo: 100 ppm/C; EIA_Code: E96; U/M: EA
R134 = CRCW060315R0FKEA: RES, 15.0 ohm, 1%, 0.1W, 0603; Manufacturer: Vishay-Dale; CompType: Resistor; Res_ohm: 15; Value_Code: 15R0; Tolerance_%: 1; Power_W: 0.1; VDC_V: 75; TempCo: 100 ppm/C; EIA_Code: E96; U/M: EA
R138 = ERJ-8ENF2001V: RES, 2.00 k, 1%, 0.25 W, 1206; Manufacturer: Panasonic; CompType: Resistor; Value: 2.00k; Res_ohm: 2000; Value_Code: 2k00; Tolerance_%: 1; Power_W: 0.25; Value2: 0.25W; VDC_V: 200; TempCo: 100 ppm/C; SizeArea_mm2: 5.12; SizeX_mm: 3.2; SizeY_mm: 1.6; SizeZ_mm: 1.35; EIA_Code: E96; U/M: EA; AEC Category: Q200
R139 = CRCW060348K7FKEA: RES, 48.7 k, 1%, 0.1 W, 0603; Manufacturer: Vishay-Dale; CompType: Resistor; Value: 48.7k; Res_ohm: 48700; Value_Code: 48k7; Tolerance_%: 1; Power_W: 0.1; Value2: 0.1W; VDC_V: 75; TempCo: 100 ppm/C; SizeArea_mm2: 1.28; SizeX_mm: 1.6; SizeY_mm: 0.8; EIA_Code: E96; U/M: EA; AEC Category: Q200
R140 = CRCW0603100KFKEA: RES, 100k ohm, 1%, 0.1W, 0603; Manufacturer: Vishay-Dale; CompType: Resistor; Res_ohm: 100000; Tolerance_%: 1; Power_W: 0.1; VDC_V: 75; TempCo: 100 ppm/C; EIA_Code: E96; U/M: EA
R141 = CRCW060323K7FKEA: RES, 23.7 k, 1%, 0.1 W, 0603; Manufacturer: Vishay-Dale; CompType: Resistor; Value: 23.7k; Res_ohm: 23700; Value_Code: 23k7; Tolerance_%: 1; Power_W: 0.1; Value2: 0.1W; VDC_V: 75; TempCo: 100 ppm/C; SizeArea_mm2: 1.28; SizeX_mm: 1.6; SizeY_mm: 0.8; EIA_Code: E96; U/M: EA; AEC Category: Q200
R142 = CRCW060316K2FKEA: RES, 16.2 k, 1%, 0.1 W, 0603; Manufacturer: Vishay-Dale; CompType: Resistor; Value: 16.2k; Res_ohm: 16200; Value_Code: 16k2; Tolerance_%: 1; Power_W: 0.1; Value2: 0.1W; VDC_V: 75; TempCo: 100 ppm/C; SizeArea_mm2: 1.28; SizeX_mm: 1.6; SizeY_mm: 0.8; EIA_Code: E96; U/M: EA; AEC Category: Q200
R143 = CRCW060320K5FKEA: RES, 20.5 k, 1%, 0.1 W, 0603; Manufacturer: Vishay-Dale; CompType: Resistor; Value: 20.5k; Res_ohm: 20500; Value_Code: 20k5; Tolerance_%: 1; Power_W: 0.1; Value2: 0.1W; VDC_V: 75; TempCo: 100 ppm/C; SizeArea_mm2: 1.28; SizeX_mm: 1.6; SizeY_mm: 0.8; EIA_Code: E96; U/M: EA; AEC Category: Q200
R144 = CRCW06032K05FKEA: RES, 2.05 k, 1%, 0.1 W, 0603; Manufacturer: Vishay-Dale; CompType: Resistor; Value: 2.05k; Res_ohm: 2050; Value_Code: 2k05; Tolerance_%: 1; Power_W: 0.1; Value2: 0.1W; VDC_V: 75; TempCo: 100 ppm/C; SizeArea_mm2: 1.28; SizeX_mm: 1.6; SizeY_mm: 0.8; EIA_Code: E96; U/M: EA; AEC Category: Q200
R146 = CRCW060341K2FKEA: RES, 41.2 k, 1%, 0.1 W, 0603; Manufacturer: Vishay-Dale; CompType: Resistor; Value: 41.2k; Res_ohm: 41200; Value_Code: 41k2; Tolerance_%: 1; Power_W: 0.1; Value2: 0.1W; VDC_V: 75; TempCo: 100 ppm/C; SizeArea_mm2: 1.28; SizeX_mm: 1.6; SizeY_mm: 0.8; EIA_Code: E96; U/M: EA; AEC Category: Q200
RT100 = B57237S229M: Thermistor NTC, 2.2 ohm, 20%, 15x7mm; Manufacturer: TDK; Tolerance_%: 20; Power_W: 3.1; TaMin_C: -55; TaMax_C: 170; U/M: EA
RV100 = S10K275E2: Varistor 275V RMS 10MM Radial, TH; Manufacturer: EPCOS Inc; SymbolCreator: a0412235
T100 = 750316711: Transformer, 1500 uH, EE13/7/4, TH; Manufacturer: Wurth Elektronik; SymbolCreator: Altium; Value: 1.5mH; Lp: 1500; DCR_ohm: 10.35; Ns1toNp: 0.143; Rs1: 1.6; SizeAreaWB_mm2: 352.914; SizeArea_mm2: 280.574; SizeX_mm: 20.45; SizeY_mm: 13.72; SizeZ_mm: 10.16
U100 = UCC28051DR: PFC Controller for low to medium power applications requiring compliance with IEC 61000-3-2, D0008A (SOIC-8); Manufacturer: Texas Instruments; SymbolCreator: a0412238; SizeArea_mm2: 30.38; SizeAreaWB_mm2: 56.58; SizeX_mm: 4.9; SizeY_mm: 6.2; SizeZ_mm: 1.75; CompType: IC; U/M: EA
U101 = TMP300BIDCKR: Resistor-Programmable, up to 18V-Capable Temp Switch and Analog Out Sensor, DCK0006A (SOT-6); Alternate PartNumber: TMP300BIDCKT; Manufacturer: Texas Instruments; SymbolCreator: a0412235; SizeArea_mm2: 4.2; SizeAreaWB_mm2: 9.3; SizeX_mm: 2.1; SizeY_mm: 2; SizeZ_mm: 1.1; CompType: IC; U/M: EA
U102 = LM393D: Dual Comparator, D0008A; Manufacturer: Texas Instruments; CompType: OpAmp IC
U103 = UCC28910DR: High-Voltage Flyback Switcher with Primary-Side Regulation and Constant-Current Control, D0007A (SOIC-7); Manufacturer: Texas Instruments; SymbolCreator: a0412235; SizeArea_mm2: 29.4; SizeAreaWB_mm2: 55.2; SizeX_mm: 6; SizeY_mm: 4.9; SizeZ_mm: 1.75; CompType: IC; U/M: EA
U104 = LM4040CIM3-5.0: Precision Micropower Shunt Voltage Reference, 3-pin SOT-23; Manufacturer: Texas Instruments; PackageTopMarking: R5C*XTT; PowerWise: N; CompType: Voltage Reference IC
